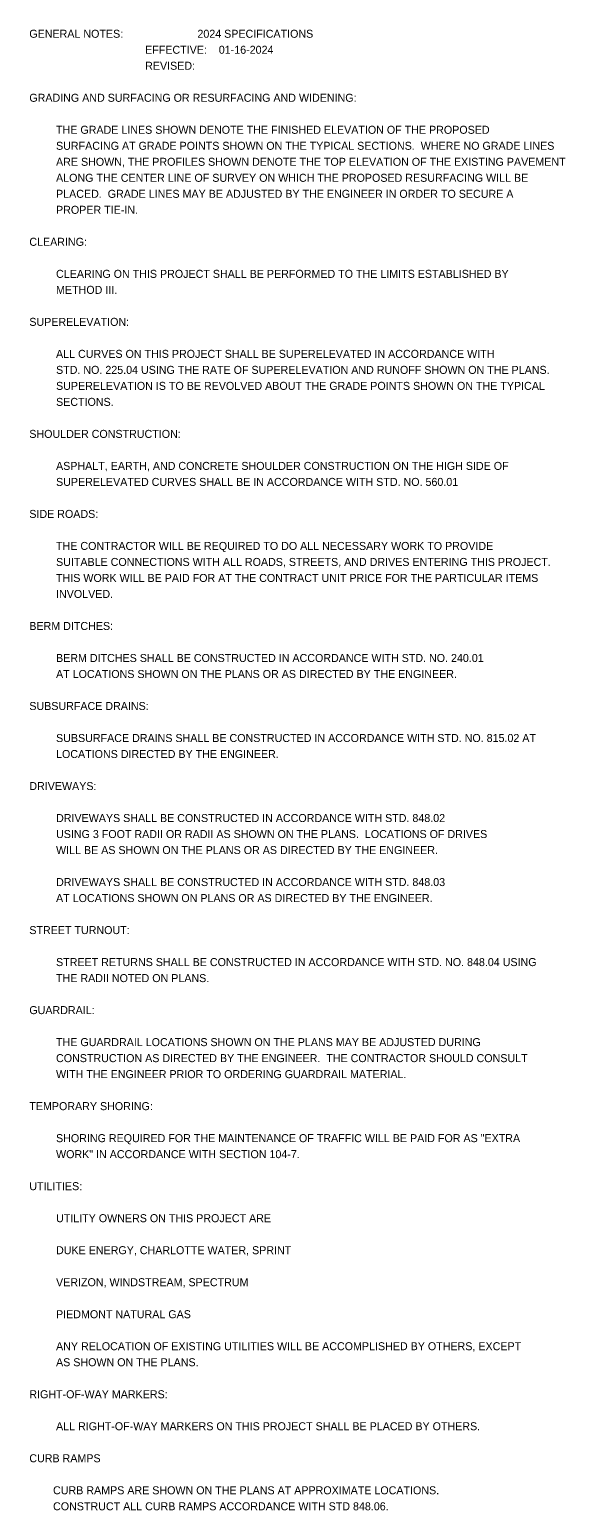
# Model space of a CAD drawing. Extents: x -1492 to 2447, y -56 to 1953.
# Drawn here: x 2044 to 2447, y -56 to 1054 of the extents above; entities that cross this region are included whole.
import ezdxf

# ---------------------------------------------------------------- set-up
doc = ezdxf.new("R2010")
doc.units = 0
doc.layers.add('Sheet Data Text CELL', color=7, linetype='Continuous')

msp = doc.modelspace()

# ---------------------------------------------------------------- texts
at = {"layer": 'Sheet Data Text CELL'}
for s, p in [('GENERAL NOTES:                         2024 SPECIFICATIONS', (2044.2, 1047.8)), ('                                       EFFECTIVE:    01-16-2024', (2044.2, 1035.8)), ('                                       REVISED:      ', (2044.2, 1023.8)), ('GRADING AND SURFACING OR RESURFACING AND WIDENING:  ', (2044.2, 999.8)), ('         THE GRADE LINES SHOWN DENOTE THE FINISHED ELEVATION OF THE PROPOSED ', (2044.2, 975.8)), ('         SURFACING AT GRADE POINTS SHOWN ON THE TYPICAL SECTIONS.  WHERE NO GRADE LINES ', (2044.2, 963.8)), ('         ARE SHOWN, THE PROFILES SHOWN DENOTE THE TOP ELEVATION OF THE EXISTING PAVEMENT ', (2044.2, 951.8)), ('         ALONG THE CENTER LINE OF SURVEY ON WHICH THE PROPOSED RESURFACING WILL BE ', (2044.2, 939.8)), ('         PLACED.  GRADE LINES MAY BE ADJUSTED BY THE ENGINEER IN ORDER TO SECURE A ', (2044.2, 927.8)), ('         PROPER TIE-IN.  ', (2044.2, 915.8)), ('CLEARING:  ', (2044.2, 891.8)), ('         CLEARING ON THIS PROJECT SHALL BE PERFORMED TO THE LIMITS ESTABLISHED BY ', (2044.2, 867.8)), ('         METHOD III.', (2044.2, 855.8)), ('SUPERELEVATION:  ', (2044.2, 831.8)), ('         ALL CURVES ON THIS PROJECT SHALL BE SUPERELEVATED IN ACCORDANCE WITH', (2044.2, 807.8)), ('         STD. NO. 225.04 USING THE RATE OF SUPERELEVATION AND RUNOFF SHOWN ON THE PLANS.', (2044.2, 795.8)), ('         SUPERELEVATION IS TO BE REVOLVED ABOUT THE GRADE POINTS SHOWN ON THE TYPICAL ', (2044.2, 783.8)), ('         SECTIONS.  ', (2044.2, 771.8)), ('SHOULDER CONSTRUCTION:  ', (2044.2, 747.8)), ('         ASPHALT, EARTH, AND CONCRETE SHOULDER CONSTRUCTION ON THE HIGH SIDE OF', (2044.2, 723.8)), ('         SUPERELEVATED CURVES SHALL BE IN ACCORDANCE WITH STD. NO. 560.01', (2044.2, 711.8)), ('SIDE ROADS:  ', (2044.2, 687.8)), ('         THE CONTRACTOR WILL BE REQUIRED TO DO ALL NECESSARY WORK TO PROVIDE ', (2044.2, 663.8)), ('         SUITABLE CONNECTIONS WITH ALL ROADS, STREETS, AND DRIVES ENTERING THIS PROJECT.  ', (2044.2, 651.8)), ('         THIS WORK WILL BE PAID FOR AT THE CONTRACT UNIT PRICE FOR THE PARTICULAR ITEMS ', (2044.2, 639.8)), ('         INVOLVED.  ', (2044.2, 627.8)), ('BERM DITCHES:  ', (2044.2, 603.8)), ('         BERM DITCHES SHALL BE CONSTRUCTED IN ACCORDANCE WITH STD. NO. 240.01 ', (2044.2, 579.8)), ('         AT LOCATIONS SHOWN ON THE PLANS OR AS DIRECTED BY THE ENGINEER.  ', (2044.2, 567.8)), ('SUBSURFACE DRAINS:', (2044.2, 543.8)), ('         SUBSURFACE DRAINS SHALL BE CONSTRUCTED IN ACCORDANCE WITH STD. NO. 815.02 AT ', (2044.2, 519.8)), ('         LOCATIONS DIRECTED BY THE ENGINEER.  ', (2044.2, 507.8)), ('DRIVEWAYS:  ', (2044.2, 483.8)), ('         DRIVEWAYS SHALL BE CONSTRUCTED IN ACCORDANCE WITH STD. 848.02', (2044.2, 459.8)), ('         USING 3 FOOT RADII OR RADII AS SHOWN ON THE PLANS.  LOCATIONS OF DRIVES', (2044.2, 447.8)), ('         WILL BE AS SHOWN ON THE PLANS OR AS DIRECTED BY THE ENGINEER.  ', (2044.2, 435.8)), ('         DRIVEWAYS SHALL BE CONSTRUCTED IN ACCORDANCE WITH STD. 848.03', (2044.2, 411.8)), ('         AT LOCATIONS SHOWN ON PLANS OR AS DIRECTED BY THE ENGINEER.  ', (2044.2, 399.8)), ('STREET TURNOUT:  ', (2044.2, 375.8)), ('         STREET RETURNS SHALL BE CONSTRUCTED IN ACCORDANCE WITH STD. NO. 848.04 USING ', (2044.2, 351.8)), ('         THE RADII NOTED ON PLANS.  ', (2044.2, 339.8)), ('GUARDRAIL:  ', (2044.2, 315.8)), ('         THE GUARDRAIL LOCATIONS SHOWN ON THE PLANS MAY BE ADJUSTED DURING ', (2044.2, 291.8)), ('         CONSTRUCTION AS DIRECTED BY THE ENGINEER.  THE CONTRACTOR SHOULD CONSULT', (2044.2, 279.8)), ('         WITH THE ENGINEER PRIOR TO ORDERING GUARDRAIL MATERIAL.', (2044.2, 267.8)), ('TEMPORARY SHORING:  ', (2044.2, 243.8)), ('         SHORING REQUIRED FOR THE MAINTENANCE OF TRAFFIC WILL BE PAID FOR AS "EXTRA ', (2044.2, 219.8)), ('         WORK" IN ACCORDANCE WITH SECTION 104-7.  ', (2044.2, 207.8)), ('UTILITIES:  ', (2044.2, 183.8)), ('         UTILITY OWNERS ON THIS PROJECT ARE  ', (2044.2, 159.8)), ('         DUKE ENERGY, CHARLOTTE WATER, SPRINT', (2044.2, 135.8)), ('         VERIZON, WINDSTREAM, SPECTRUM', (2044.2, 111.8)), ('         PIEDMONT NATURAL GAS', (2044.2, 87.8)), ('         ANY RELOCATION OF EXISTING UTILITIES WILL BE ACCOMPLISHED BY OTHERS, EXCEPT ', (2044.2, 63.8)), ('         AS SHOWN ON THE PLANS.  ', (2044.2, 51.8)), ('RIGHT-OF-WAY MARKERS:  ', (2044.2, 27.8)), ('         ALL RIGHT-OF-WAY MARKERS ON THIS PROJECT SHALL BE PLACED BY OTHERS.  ', (2044.2, 3.8)), ('CURB RAMPS', (2044.2, -20.2)), ('        CURB RAMPS ARE SHOWN ON THE PLANS AT APPROXIMATE LOCATIONS.', (2044.2, -44.2)), ('        CONSTRUCT ALL CURB RAMPS ACCORDANCE WITH STD 848.06.', (2044.2, -56.2))]:
    msp.add_text(s, height=6, dxfattribs=at).set_placement(p)

doc.saveas('drawing.dxf')
